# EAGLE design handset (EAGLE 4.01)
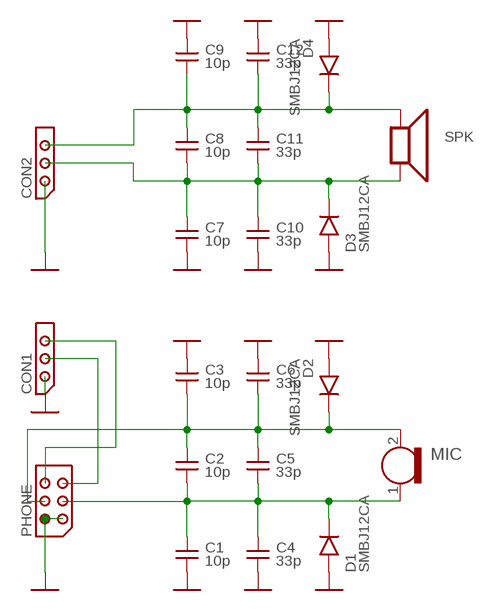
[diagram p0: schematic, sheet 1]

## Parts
C1  10p  CAP0805  [0805]
C2  10p  CAP0805  [0805]
C3  10p  CAP0805  [0805]
C4  33p  CAP0805  [0805]
C5  33p  CAP0805  [0805]
C6  33p  CAP0805  [0805]
C7  10p  CAP0805  [0805]
C8  10p  CAP0805  [0805]
C9  10p  CAP0805  [0805]
C10  33p  CAP0805  [0805]
C11  33p  CAP0805  [0805]
C12  33p  CAP0805  [0805]
CON1  CON03X1  [CON03X1]
CON2  CON03X1  [CON03X1]
D1  SMBJ12CA  DIO-SMB  [DO214AA]
D2  SMBJ12CA  DIO-SMB  [DO214AA]
D3  SMBJ12CA  DIO-SMB  [DO214AA]
D4  SMBJ12CA  DIO-SMB  [DO214AA]
MIC  MICV980  [M_V980]
PHONE  CON03X2  [CON03X2]
SPK  SPKV3  [M_V3]

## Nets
GND: C1.1 C3.2 C4.1 C6.2 C7.1 C9.2 C10.1 C12.2 CON1.1 CON2.1 D1.A D2.A D3.A D4.A PHONE.1 PHONE.2 ; supply symbol labelled GND*
MIC_N: C1.2 C2.1 C4.2 C5.1 D1.C MIC.1(GND) PHONE.3
MIC_P: C2.2 C3.1 C5.2 C6.1 D2.C MIC.2(S) PHONE.4
N$1: CON1.2 PHONE.5
N$2: CON1.3 PHONE.6
SPK_N: C7.2 C8.1 C10.2 C11.1 CON2.2 D3.C SPK.2(-)
SPK_P: C8.2 C9.1 C11.2 C12.1 CON2.3 D4.C SPK.1(+)

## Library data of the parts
C1-C12 = discrete:CAP0805
CON1 CON2 = connector:CON03X1
D1-D4 = discrete:DIO-SMB
MIC = speaker:MIC
PHONE = connector:CON03X2
SPK = speaker:SPK

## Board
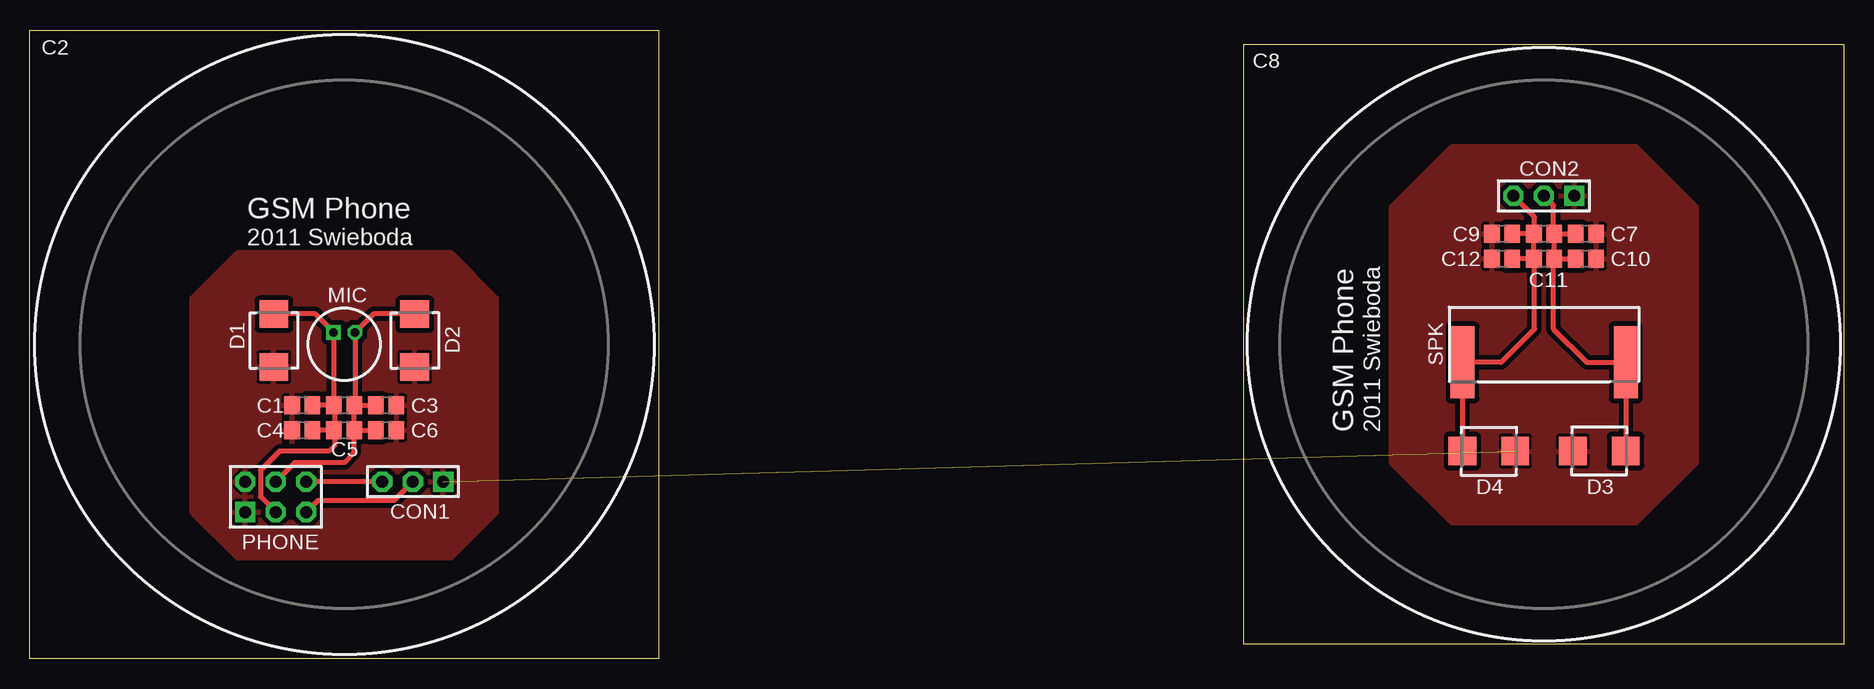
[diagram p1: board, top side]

Size 151.2 x 52.4 mm. Coordinates in mm from the lower left corner, seen from the top.
Outline: 101.2,51.2 151.2,51.2 151.2,1.2 101.2,1.2 101.2,51.2
Outline: 0,52.4 52.4,52.4 52.4,0 0,0 0,52.4
Copper layers used: Top

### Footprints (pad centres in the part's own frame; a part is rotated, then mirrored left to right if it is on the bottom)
0805 = smd 1.3 x 1.5: 1 -0.85,0; 2 0.85,0
CON03X1 = drill 1 pad 1.676 square: 1 0,0 | drill 1 pad 1.676 octagon: 2 2.54,0; 3 5.08,0
DO214AA = smd 2.3 x 2.4: A 2.2,0; C -2.2,0
M_V980 = drill 0.7 square: 1 -0.9,1 | drill 0.7 octagon: 2 0.9,1
CON03X2 = drill 1 pad 1.676 square: 1 0,0 | drill 1 pad 1.676 octagon: 2 0,2.54; 3 2.54,0; 4 2.54,2.54; 5 5.08,0; 6 5.08,2.54
M_V3 = smd 2 x 6: 1 -6.8,-1.5; 2 6.8,-1.5

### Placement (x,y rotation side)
C1  22.71,21.12 0 top
C2  26.2,21.12 0 top
C3  29.69,21.12 0 top
C4  22.71,19.06 0 top
C5  26.2,19.06 0 top
C6  29.69,19.06 0 top
C7  129.69,35.41 180 top
C8  126.2,35.41 180 top
C9  122.71,35.41 180 top
C10  129.69,33.34 180 top
C11  126.2,33.34 180 top
C12  122.71,33.34 180 top
CON1  34.45,14.77 180 top
CON2  128.74,38.58 180 top
D1  20.33,26.52 270 top
D2  32.07,26.52 270 top
D3  130.8,17.31 180 top
D4  121.6,17.31 0 top
MIC  26.2,26.2 0 top
PHONE  17.95,12.23 0 top
SPK  126.2,26.2 0 top

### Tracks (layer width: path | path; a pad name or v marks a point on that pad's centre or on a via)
GND  (1 unrouted)
  pour Top (isolate 0.406): 118.58,42.71 133.82,42.71 138.9,37.63 138.9,16.36 133.82,11.28 118.58,11.28 113.5,16.36 113.5,37.63
  pour Top (isolate 0.406): 35.09,8.42 38.9,12.23 38.9,30.01 35.09,33.82 17.31,33.82 13.5,30.01 13.5,12.23 17.31,8.42
MIC_N
  Top 0.406: 25.3,21.12 MIC.1 23.76,28.74 20.33,28.74 D1.C | 25.3,21.12 C2.1 25.41,21.12 25.41,19.06 | PHONE.3 19.22,13.5 19.22,15.72 20.8,17.31 24.93,17.31 25.41,17.79 25.41,18.9 25.35,18.95 C5.1 25.41,19.06 | 25.41,19.06 | 25.41,19.06 C4.2 | 25.41,19.06 | 25.3,21.12 C1.2 | D1.C
MIC_P
  Top 0.406: PHONE.4 22.07,16.36 26.2,16.36 26.99,17.15 26.99,19.06 | C5.2 | 26.99,19.06 C5.2 | 26.99,21.12 26.99,19.06 | 26.99,21.12 C2.2 | 27.1,21.12 MIC.2 28.64,28.74 32.05,28.74 D2.C | 27.1,21.12 26.99,21.12 | C5.2 26.99,19.06 | 26.99,19.06 C6.1 | 26.99,19.06 | 27.1,21.12 C3.1
N$1
  Top 0.406: PHONE.5 23.98,13.18 30.33,13.18 CON1.2
N$2
  Top 0.406: CON1.3 PHONE.6
SPK_N
  Top 0.406: CON2.2 126.99,37.79 126.99,35.41 | C11.1 C8.1 126.99,35.41 | 126.99,35.41 C7.2 | C11.1 C10.2 | C11.1 126.99,33.34 126.99,27.47 129.76,24.7 SPK.2 133,17.15 | 133,17.15 133.03,17.15 | 133,17.15 D3.C
SPK_P
  Top 0.406: CON2.3 125.41,36.84 125.41,35.41 C8.2 | C8.2 C9.1 | C11.2 C8.2 | C11.2 125.25,33.34 | C11.2 125.41,33.34 125.41,33.19 | C11.2 C12.1 | 125.41,33.19 125.41,27.47 122.64,24.7 SPK.1 D4.C 119.06,17.31 | 125.41,33.19

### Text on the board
tNames: GSM Phone | 2011 Swieboda | GSM Phone | 2011 Swieboda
